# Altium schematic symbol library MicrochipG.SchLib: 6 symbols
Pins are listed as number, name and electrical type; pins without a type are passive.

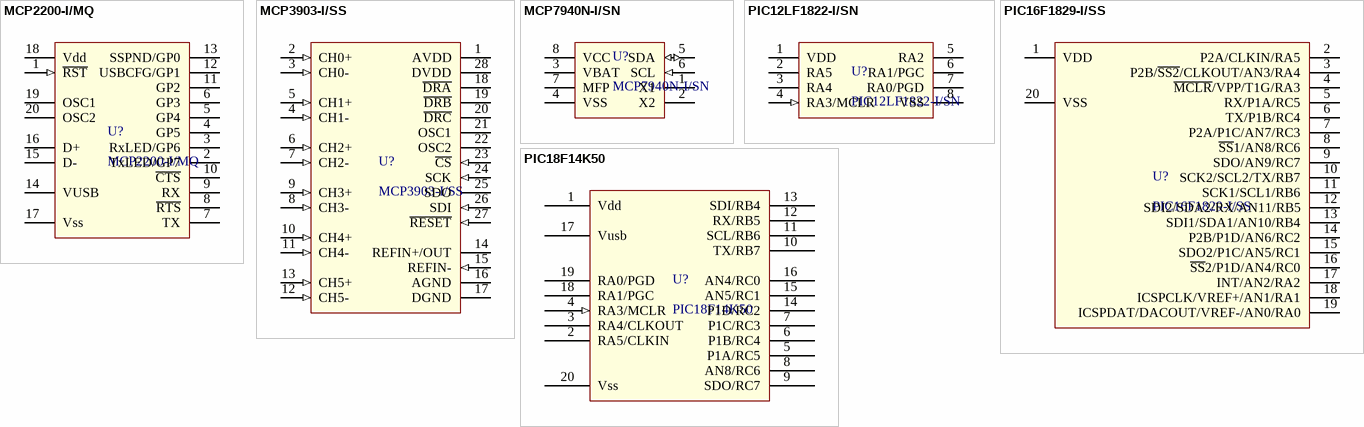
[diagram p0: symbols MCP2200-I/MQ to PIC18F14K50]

## MCP2200-I/MQ
designator U?
USB 2.0 UART
footprint QFN-ML20_N (Footprint not found)
footprint QFN-ML20_M (Footprint not found)
footprint QFN-ML20_L (Footprint not found)
pins: 1 ~{RST} (in), 2 TxLED/GP7, 3 RxLED/GP6, 4 GP5, 5 GP4, 6 GP3, 7 TX, 8 ~{RTS}, 9 RX, 10 ~{CTS}, 11 GP2, 12 USBCFG/GP1, 13 SSPND/GP0, 14 VUSB, 15 D-, 16 D+, 17 Vss (power), 18 Vdd (power), 19 OSC1, 20 OSC2

## MCP3903-I/SS
designator U?
6-channel, 24-bit Analog Front End
footprint SSOP-28 (SSOP, Plastic; 28 Leads; Body Width 5.2 mm; Pitch 0.65 mm)
pins: 1 AVDD (power), 2 CH0+ (in), 3 CH0- (in), 4 CH1- (in), 5 CH1+ (in), 6 CH2+ (in), 7 CH2- (in), 8 CH3- (in), 9 CH3+ (in), 10 CH4+ (in), 11 CH4- (in), 12 CH5- (in), 13 CH5+ (in), 14 REFIN+/OUT, 15 REFIN- (in), 16 AGND (power), 17 DGND (power), 18 ~{DRA} (oc), 19 ~{DRB} (oc), 20 ~{DRC} (oc), 21 OSC1, 22 OSC2, 23 ~{CS} (in), 24 SCK (in), 25 SDO (hiz), 26 SDI (in), 27 ~{RESET} (in), 28 DVDD (power)

## MCP7940N-I/SN
designator U?
I2C Real-Time Clock/Calendar
footprint SOIC127P600-8N (SOIC, 8-Leads, Body 4.9x3.9mm, Pitch 1.27mm, IPC Medium Density)
pins: 1 X1, 2 X2, 3 VBAT, 4 VSS (power), 5 SDA (io), 6 SCL (in), 7 MFP, 8 VCC (power)

## PIC12LF1822-I/SN
designator U?
footprint SOIC127P600-8N (SOIC, 8-Leads, Body 4.9x3.9mm, Pitch 1.27mm, IPC Medium Density)
pins: 1 VDD (power), 2 RA5, 3 RA4, 4 RA3/MCLR (in), 5 RA2, 6 RA1/PGC, 7 RA0/PGD, 8 VSS (power)

## PIC16F1829-I/SS
designator U?
footprint SSOP-20 (SSOP, Plastic; 20 Leads; Body Width 5.3 mm; Pitch 0.65 mm)
pins: 1 VDD, 2 P2A/CLKIN/RA5, 3 P2B/~{SS2}/CLKOUT/AN3/RA4, 4 ~{MCLR}/VPP/T1G/RA3, 5 RX/P1A/RC5, 6 TX/P1B/RC4, 7 P2A/P1C/AN7/RC3, 8 ~{SS}1/AN8/RC6, 9 SDO/AN9/RC7, 10 SCK2/SCL2/TX/RB7, 11 SCK1/SCL1/RB6, 12 SDI2/SDA2/RX/AN11/RB5, 13 SDI1/SDA1/AN10/RB4, 14 P2B/P1D/AN6/RC2, 15 SDO2/P1C/AN5/RC1, 16 ~{SS}2/P1D/AN4/RC0, 17 INT/AN2/RA2, 18 ICSPCLK/VREF+/AN1/RA1, 19 ICSPDAT/DACOUT/VREF-/AN0/RA0, 20 VSS

## PIC18F14K50
designator U?
footprint SSOP20_M (Footprint not found)
pins: 1 Vdd (power), 2 RA5/CLKIN, 3 RA4/CLKOUT, 4 RA3/MCLR (in), 5 P1A/RC5, 6 P1B/RC4, 7 P1C/RC3, 8 AN8/RC6, 9 SDO/RC7, 10 TX/RB7, 11 SCL/RB6, 12 RX/RB5, 13 SDI/RB4, 14 P1D/RC2, 15 AN5/RC1, 16 AN4/RC0, 17 Vusb, 18 RA1/PGC, 19 RA0/PGD, 20 Vss (power)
